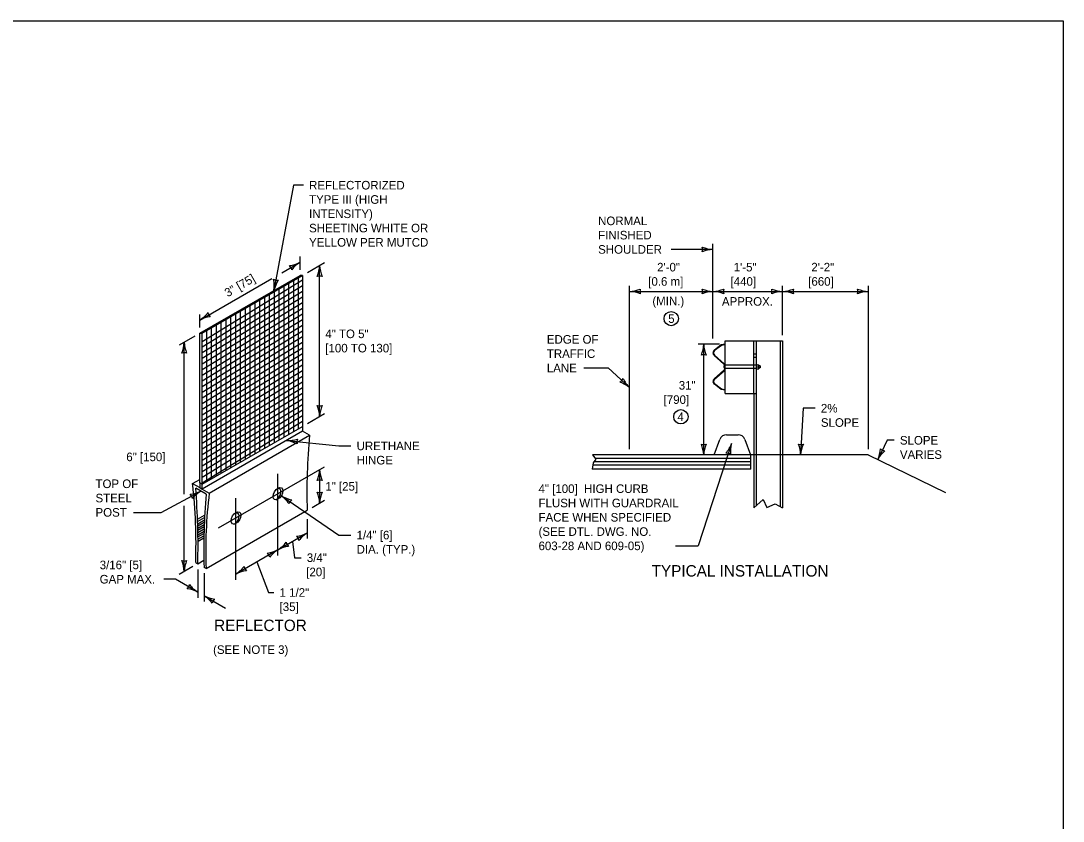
# Model space of a CAD drawing. Extents: x 49991.4 to 50021, y 49987.6 to 50011.4.
# Drawn here: x 50009.46 to 50016.75, y 49993.4 to 49999 of the extents above; entities that cross this region are included whole.
import ezdxf

# ---------------------------------------------------------------- set-up
doc = ezdxf.new("R2010")
doc.units = 0
for name, color, linetype in [('Level 1', 7, 'Continuous'), ('Level 2', 7, 'Continuous'), ('Level 3', 7, 'Continuous'), ('Level 4', 7, 'Continuous'), ('Level 5', 7, 'Continuous')]:
    doc.layers.add(name, color=color, linetype=linetype)

msp = doc.modelspace()

# ---------------------------------------------------------------- linework, layer by layer
at = {"layer": 'Level 1'}
for p, q in [((50010.7126, 49996.8127), (50011.4141, 49997.2177)), ((50010.7295, 49996.8127), (50011.4309, 49997.2177)), ((50011.4037, 49996.1458), (50011.4037, 49997.202)), ((50011.4309, 49997.2177), (50011.4141, 49997.2177)), ((50011.4309, 49997.2177), (50011.4309, 49996.1615)), ((50010.7295, 49996.7565), (50011.4309, 49997.1868)), ((50010.7295, 49996.7169), (50011.4309, 49997.1472)), ((50011.2687, 49996.0679), (50011.2687, 49997.124)), ((50011.3025, 49996.0874), (50011.3025, 49997.1435)), ((50011.3362, 49996.1069), (50011.3362, 49997.163)), ((50011.37, 49996.1263), (50011.37, 49997.1825)), ((50010.7295, 49996.6773), (50011.4309, 49997.1076)), ((50010.7295, 49996.6378), (50011.4309, 49997.068)), ((50011.1675, 49996.0094), (50011.1675, 49997.0656)), ((50011.2012, 49996.0289), (50011.2012, 49997.085)), ((50011.235, 49996.0484), (50011.235, 49997.1045)), ((50010.7295, 49996.5982), (50011.4309, 49997.0284)), ((50010.7295, 49996.5586), (50011.4309, 49996.9888)), ((50011.0325, 49995.9315), (50011.0325, 49996.9876)), ((50011.0662, 49995.951), (50011.0662, 49997.0071)), ((50011.1, 49995.9705), (50011.1, 49997.0266)), ((50011.1337, 49995.9899), (50011.1337, 49997.0461)), ((50010.7295, 49996.519), (50011.4309, 49996.9492)), ((50010.7295, 49996.4794), (50011.4309, 49996.9096)), ((50010.8975, 49995.8535), (50010.8975, 49996.9097)), ((50010.9312, 49995.873), (50010.9312, 49996.9292)), ((50010.965, 49995.8925), (50010.965, 49996.9486)), ((50010.9987, 49995.912), (50010.9987, 49996.9681)), ((50010.7295, 49996.4398), (50011.4309, 49996.87)), ((50010.7295, 49996.4002), (50011.4309, 49996.8304)), ((50010.7625, 49995.7756), (50010.7625, 49996.8317)), ((50010.7962, 49995.7951), (50010.7962, 49996.8512)), ((50010.83, 49995.8146), (50010.83, 49996.8707)), ((50010.8637, 49995.8341), (50010.8637, 49996.8902)), ((50010.7126, 49995.7663), (50010.7126, 49996.8127)), ((50010.7126, 49996.8127), (50010.7295, 49996.8127)), ((50010.7295, 49995.7565), (50010.7295, 49996.8127)), ((50010.7295, 49996.3606), (50011.4309, 49996.7909)), ((50014.3868, 49996.7592), (50014.7881, 49996.7592)), ((50014.3868, 49996.392), (50014.3868, 49996.7592)), ((50014.6028, 49996.7592), (50014.6028, 49995.9612)), ((50014.7722, 49996.7592), (50014.7722, 49995.9612)), ((50014.7881, 49996.7592), (50014.7881, 49995.9612)), ((50010.7295, 49996.321), (50011.4309, 49996.7513)), ((50010.7295, 49996.2814), (50011.4309, 49996.7117)), ((50014.3595, 49996.7313), (50014.3116, 49996.6954)), ((50014.3608, 49996.7284), (50014.3134, 49996.6929)), ((50014.3868, 49996.7362), (50014.3595, 49996.7313)), ((50014.3868, 49996.7329), (50014.3608, 49996.7284)), ((50010.7295, 49996.2418), (50011.4309, 49996.6721)), ((50010.7295, 49996.2022), (50011.4309, 49996.6325)), ((50014.3102, 49996.657), (50014.3785, 49996.5975)), ((50014.3122, 49996.6594), (50014.3806, 49996.5998)), ((50010.7295, 49996.1626), (50011.4309, 49996.5929)), ((50010.7295, 49996.1231), (50011.4309, 49996.5533)), ((50014.3102, 49996.4944), (50014.3783, 49996.5538)), ((50014.3122, 49996.4921), (50014.3817, 49996.5526)), ((50014.3853, 49996.578), (50014.3775, 49996.578)), ((50014.6028, 49996.5943), (50014.6044, 49996.5943)), ((50014.6028, 49996.5614), (50014.6044, 49996.5614)), ((50014.6044, 49996.5943), (50014.6044, 49996.5778)), ((50014.6044, 49996.5912), (50014.6217, 49996.5912)), ((50014.6044, 49996.578), (50014.6217, 49996.578)), ((50014.6044, 49996.5778), (50014.6044, 49996.5614)), ((50014.6044, 49996.5648), (50014.6217, 49996.5648)), ((50014.6217, 49996.578), (50014.6217, 49996.5912)), ((50014.6321, 49996.5858), (50014.6217, 49996.5858)), ((50014.6217, 49996.578), (50014.6217, 49996.5648)), ((50014.6321, 49996.5702), (50014.6217, 49996.5702)), ((50014.6321, 49996.5858), (50014.6321, 49996.5702)), ((50010.7295, 49996.0835), (50011.4309, 49996.5137)), ((50010.7295, 49996.0439), (50011.4309, 49996.4741)), ((50010.7295, 49996.0043), (50011.4309, 49996.4345)), ((50010.7295, 49995.9647), (50011.4309, 49996.3949)), ((50014.3595, 49996.4197), (50014.3116, 49996.456)), ((50014.3608, 49996.4227), (50014.3134, 49996.4586)), ((50014.3868, 49996.4149), (50014.3595, 49996.4197)), ((50014.3868, 49996.4182), (50014.3608, 49996.4227)), ((50010.7295, 49995.9251), (50011.4309, 49996.3553)), ((50014.3868, 49996.392), (50014.6028, 49996.392)), ((50014.5869, 49996.392), (50014.5869, 49995.9612)), ((50010.7295, 49995.8855), (50011.4309, 49996.3157)), ((50010.7295, 49995.8459), (50011.4309, 49996.2761)), ((50010.7295, 49995.8063), (50011.4309, 49996.2366)), ((50010.7295, 49995.7667), (50011.4309, 49996.197)), ((50010.7295, 49995.7565), (50011.4309, 49996.1615)), ((50011.4309, 49996.1278), (50010.7295, 49995.7228)), ((50011.4309, 49996.1615), (50011.4309, 49996.1278)), ((50011.4309, 49996.1574), (50011.4309, 49996.1574)), ((50011.4811, 49996.099), (50011.4309, 49996.1278)), ((50014.3972, 49996.1033), (50014.4772, 49996.1033)), ((50010.7796, 49995.694), (50011.4811, 49996.099)), ((50014.3105, 49995.9612), (50014.3502, 49996.0704)), ((50014.5242, 49996.0704), (50014.5639, 49995.9612)), ((50013.4596, 49995.9612), (50013.4826, 49995.9309)), ((50015.3875, 49995.9612), (50013.4596, 49995.9612)), ((50014.5664, 49995.8613), (50014.5664, 49995.9612)), ((50015.3875, 49995.9612), (50015.9268, 49995.6982)), ((50013.4634, 49995.9064), (50013.456, 49995.8613)), ((50014.5664, 49995.8892), (50013.4606, 49995.8892)), ((50013.4826, 49995.9309), (50013.4634, 49995.9064)), ((50014.5664, 49995.9132), (50013.4687, 49995.9132)), ((50014.5664, 49995.9372), (50013.4778, 49995.9372)), ((50014.5664, 49995.8613), (50013.456, 49995.8613)), ((50010.6627, 49995.7615), (50010.7126, 49995.7903)), ((50010.6627, 49995.7615), (50010.7126, 49995.7327)), ((50010.7295, 49995.7565), (50010.7126, 49995.7663)), ((50010.7126, 49995.7663), (50010.7126, 49995.7327)), ((50010.7295, 49995.7228), (50010.7295, 49995.7565)), ((50010.7295, 49995.7228), (50010.7295, 49995.7565)), ((50010.7577, 49995.6871), (50010.6846, 49995.7293)), ((50010.7126, 49995.7327), (50010.7295, 49995.7228)), ((50010.7295, 49995.7228), (50010.7796, 49995.694)), ((50010.6976, 49995.5112), (50010.7474, 49995.54)), ((50010.6982, 49995.4959), (50010.7466, 49995.5239)), ((50010.7577, 49995.1666), (50011.4642, 49995.5745)), ((50010.6986, 49995.4806), (50010.7458, 49995.5079)), ((50010.6991, 49995.4653), (50010.7451, 49995.4919)), ((50010.6995, 49995.45), (50010.7444, 49995.4759)), ((50010.6999, 49995.4346), (50010.7439, 49995.46)), ((50010.7002, 49995.4192), (50010.7433, 49995.4441)), ((50010.7004, 49995.4037), (50010.7429, 49995.4282)), ((50010.7006, 49995.3883), (50010.7425, 49995.4124)), ((50010.7008, 49995.3728), (50010.7421, 49995.3966)), ((50010.7009, 49995.3572), (50010.7418, 49995.3808)), ((50010.6846, 49995.2088), (50010.6992, 49995.2004)), ((50010.6992, 49995.2004), (50010.7419, 49995.225)), ((50010.7577, 49995.1666), (50010.7431, 49995.1751))]:
    msp.add_line(p, q, dxfattribs=at)
msp.add_lwpolyline([(49999.3835, 49998.9992), (50016.7501, 49998.9992), (50016.7501, 49987.7988), (49999.3835, 49987.7988)], close=True, dxfattribs=at)
for centre, radius, start, end in [((50014.3264, 49996.6757), 0.0247, 126.89692, 228.93931), ((50014.3264, 49996.6757), 0.0216, 126.89692, 228.93931), ((50014.3624, 49996.5725), 0.0246, 310.4718, 353.52997), ((50014.3624, 49996.5789), 0.0246, 6.47003, 48.93931), ((50014.3624, 49996.5789), 0.0277, 28.21928, 48.93931), ((50014.3624, 49996.5725), 0.0277, 314.1015, 331.78072), ((50014.615, 49996.5846), 0.00673, 282.91982, 80.80521), ((50014.615, 49996.5715), 0.00673, 279.19479, 77.08018), ((50014.3264, 49996.4758), 0.0247, 131.06069, 233.10308), ((50014.3264, 49996.4758), 0.0216, 131.06069, 233.10308), ((50014.3972, 49996.0533), 0.05, 90, 159.99404), ((50014.4772, 49996.0533), 0.05, 20.00596, 90), ((50015.6681, 49995.7018), 4.2058, 174.58065, 181.73332), ((50006.9878, 49995.3389), 3.6991, 357.984, 6.55893), ((50005.8293, 49995.3305), 4.8717, 358.46937, 4.69582), ((50015.1622, 49995.3052), 4.4211, 175.04388, 181.68667), ((50013.9812, 49995.2968), 3.2261, 172.92757, 182.31169)]:
    msp.add_arc(centre, radius, start, end, dxfattribs=at)
for centre, major_axis, ratio, start_param, end_param in [((50014.3853, 49996.5779), (0, 0.0118), 0.663267, 0.091019, 3.253139), ((50011.2492, 49995.6861), (0.0228, 0.0395), 0.57735, 3.80014, 6.895622), ((50010.9582, 49995.5157), (0.0214, 0.0371), 0.57735, 3.593264, 7.511454)]:
    msp.add_ellipse(centre, major_axis=major_axis, ratio=ratio, start_param=start_param, end_param=end_param, dxfattribs=at)
for centre, major_axis in [((50011.2598, 49995.6904), (0.0239, 0.0413)), ((50010.9659, 49995.5207), (0.024, 0.0415))]:
    msp.add_ellipse(centre, major_axis=major_axis, ratio=0.57735, dxfattribs=at)
at = {"layer": 'Level 2'}
for centre in [(50014.0096, 49996.9157), (50014.0771, 49996.2287)]:
    msp.add_circle(centre, 0.05, dxfattribs=at)
at = {"layer": 'Level 3'}
for p, q in [((50011.3691, 49997.8491), (50011.2321, 49997.1126)), ((50011.4376, 49997.8491), (50011.3691, 49997.8491)), ((50014.3016, 49996.7762), (50014.3016, 49997.4396)), ((50011.4141, 49997.2577), (50011.4141, 49997.35)), ((50014.3016, 49997.3996), (50014.009, 49997.3996)), ((50011.286, 49997.2361), (50011.4141, 49997.31)), ((50011.4656, 49997.2377), (50011.5859, 49997.3071)), ((50011.5512, 49996.231), (50011.5512, 49997.2871)), ((50010.7126, 49996.905), (50011.2167, 49997.1961)), ((50013.7176, 49996.0012), (50013.7176, 49997.1457)), ((50014.7881, 49996.7992), (50014.7881, 49997.1457)), ((50015.3875, 49997.1457), (50015.3875, 49996.0012)), ((50013.7176, 49997.1057), (50014.3016, 49997.1057)), ((50014.3016, 49997.1057), (50014.7881, 49997.1057)), ((50014.7881, 49997.1057), (50015.3875, 49997.1057)), ((50010.7126, 49996.8527), (50010.7126, 49996.945)), ((50010.6779, 49996.7927), (50010.57, 49996.7303)), ((50010.6046, 49995.686), (50010.6046, 49996.7503)), ((50014.3468, 49996.7362), (50014.197, 49996.7362)), ((50014.237, 49995.9612), (50014.237, 49996.7362)), ((50013.398, 49996.5702), (50013.5682, 49996.5702)), ((50013.5682, 49996.5702), (50013.7176, 49996.4324)), ((50011.4656, 49996.1815), (50011.5859, 49996.251)), ((50014.9315, 49996.2884), (50014.9132, 49995.9612)), ((50015.0162, 49996.2884), (50014.9315, 49996.2884)), ((50011.3196, 49996.0635), (50011.6852, 49996.0251)), ((50014.4314, 49996.0416), (50014.1989, 49995.3254)), ((50015.5186, 49996.0642), (50015.4549, 49995.9284)), ((50015.5686, 49996.0642), (50015.5186, 49996.0642)), ((50011.6852, 49996.0251), (50011.7698, 49996.0251)), ((50011.5512, 49995.8586), (50011.5512, 49995.6248)), ((50010.4432, 49995.5598), (50010.7211, 49995.7082)), ((50011.2837, 49995.6766), (50011.6852, 49995.4009)), ((50010.6046, 49995.1458), (50010.6046, 49995.606)), ((50011.4988, 49995.5945), (50011.5859, 49995.6448)), ((50010.2504, 49995.5598), (50010.4432, 49995.5598)), ((50011.4642, 49995.5126), (50011.4642, 49995.3759)), ((50011.2598, 49995.2979), (50011.4642, 49995.4159)), ((50011.6852, 49995.4009), (50011.7699, 49995.4009)), ((50011.362, 49995.3569), (50011.3759, 49995.2428)), ((50014.0407, 49995.3254), (50014.1989, 49995.3254)), ((50011.2598, 49995.2979), (50010.9659, 49995.1282)), ((50011.3759, 49995.2428), (50011.4218, 49995.2428)), ((50010.6646, 49995.1804), (50010.57, 49995.1258)), ((50010.6992, 49995.1604), (50010.6992, 49994.9618)), ((50010.543, 49995.092), (50010.4608, 49995.092)), ((50010.6992, 49995.0018), (50010.543, 49995.092)), ((50010.7431, 49995.1351), (50010.7431, 49994.9365)), ((50010.7431, 49994.9765), (50010.8932, 49994.8898))]:
    msp.add_line(p, q, dxfattribs=at)
msp.add_lwpolyline([(50011.1128, 49995.2131), (50011.1933, 49994.9992), (50011.2312, 49994.9992)], dxfattribs=at)
for centre, radius, start, end in [((50014.1734, 49997.3996), 0.0548, 342.13882, 17.86118), ((50014.3131, 49997.6323), 0.233, 247.92284, 267.17269), ((50014.3108, 49997.1775), 0.2223, 92.36048, 112.54399), ((50011.3109, 49997.507), 0.2223, 277.45601, 297.63952), ((50011.303, 49997.2459), 0.0548, 12.13882, 47.86118), ((50011.5404, 49997.1143), 0.233, 122.82731, 142.07716), ((50011.3291, 49997.2963), 0.2223, 337.45601, 357.63952), ((50011.7839, 49997.2986), 0.233, 182.82731, 202.07716), ((50011.5512, 49997.1589), 0.0548, 72.13882, 107.86118), ((50011.2556, 49997.2387), 0.0548, 241.60423, 277.32659), ((50011.0012, 49997.1439), 0.233, 352.29272, 11.54257), ((50011.4488, 49997.063), 0.2223, 146.92142, 167.10493), ((50013.7061, 49997.3384), 0.233, 272.82731, 292.07716), ((50013.8458, 49997.1057), 0.0548, 162.13882, 197.86118), ((50014.3108, 49997.3279), 0.2223, 247.45601, 267.63952), ((50014.1734, 49997.1057), 0.0548, 342.13882, 17.86118), ((50014.2901, 49997.3384), 0.233, 272.82731, 292.07716), ((50014.4298, 49997.1057), 0.0548, 162.13882, 197.86118), ((50014.7973, 49997.3279), 0.2223, 247.45601, 267.63952), ((50014.6599, 49997.1057), 0.0548, 342.13882, 17.86118), ((50014.7766, 49997.3384), 0.233, 272.82731, 292.07716), ((50014.9163, 49997.1057), 0.0548, 162.13882, 197.86118), ((50015.3967, 49997.3279), 0.2223, 247.45601, 267.63952), ((50015.2593, 49997.1057), 0.0548, 342.13882, 17.86118), ((50013.7085, 49996.8836), 0.2223, 67.45601, 87.63952), ((50014.3131, 49996.873), 0.233, 92.82731, 112.07716), ((50014.2925, 49996.8836), 0.2223, 67.45601, 87.63952), ((50014.7996, 49996.873), 0.233, 92.82731, 112.07716), ((50014.779, 49996.8836), 0.2223, 67.45601, 87.63952), ((50015.399, 49996.873), 0.233, 92.82731, 112.07716), ((50010.5863, 49997.1008), 0.233, 302.82731, 322.07716), ((50010.8157, 49996.7081), 0.2223, 97.45601, 117.63952), ((50010.8236, 49996.9692), 0.0548, 192.13882, 227.86118), ((50010.3825, 49996.7595), 0.2223, 337.45601, 357.63952), ((50010.8373, 49996.7618), 0.233, 182.82731, 202.07716), ((50014.0149, 49996.7454), 0.2223, 337.45601, 357.63952), ((50014.4697, 49996.7477), 0.233, 182.82731, 202.07716), ((50010.6046, 49996.6221), 0.0548, 72.13882, 107.86118), ((50014.237, 49996.608), 0.0548, 72.13882, 107.86118), ((50013.6234, 49996.5194), 0.0548, 299.45174, 335.1741), ((50013.5683, 49996.2536), 0.233, 50.14023, 69.39008), ((50013.8749, 49996.5895), 0.2223, 204.76893, 224.95244), ((50011.5512, 49996.3592), 0.0548, 252.13882, 287.86118), ((50011.3185, 49996.2195), 0.233, 2.82731, 22.07716), ((50011.7734, 49996.2218), 0.2223, 157.45601, 177.63952), ((50011.3324, 49996.2961), 0.233, 266.83568, 286.08553), ((50011.2873, 49995.8435), 0.2223, 61.46438, 81.64789), ((50011.4471, 49996.0501), 0.0548, 156.14719, 191.86955), ((50014.237, 49996.0894), 0.0548, 252.13882, 287.86118), ((50014.0043, 49995.9497), 0.233, 2.82731, 22.07716), ((50014.4591, 49995.9521), 0.2223, 157.45601, 177.63952), ((50014.223, 49996.1189), 0.2223, 319.46868, 339.65219), ((50014.6563, 49995.9807), 0.233, 164.83998, 184.08983), ((50014.9202, 49996.0892), 0.0548, 248.99463, 284.71699), ((50014.6802, 49995.9625), 0.233, 359.68312, 18.93297), ((50015.1344, 49995.9399), 0.2223, 154.31182, 174.49533), ((50014.3918, 49995.9197), 0.0548, 54.15149, 89.87385), ((50015.2393, 49996.0168), 0.233, 337.68312, 356.93297), ((50015.6521, 49995.8257), 0.2223, 132.31182, 152.49532), ((50015.5094, 49996.0444), 0.0548, 226.99462, 262.71699), ((50011.3291, 49995.8678), 0.2223, 337.45601, 357.63952), ((50011.7839, 49995.8701), 0.233, 182.82731, 202.07716), ((50011.5512, 49995.7304), 0.0548, 72.13882, 107.86118), ((50010.6246, 49995.9085), 0.2223, 275.56316, 295.74667), ((50010.6081, 49995.6478), 0.0548, 10.24597, 45.96833), ((50010.8409, 49995.5084), 0.233, 120.93446, 140.18431), ((50011.1504, 49995.4986), 0.2223, 32.97928, 53.16279), ((50011.4059, 49995.8749), 0.233, 238.35058, 257.60043), ((50011.5512, 49995.753), 0.0548, 252.13882, 287.86118), ((50011.3185, 49995.6133), 0.233, 2.82731, 22.07716), ((50011.7734, 49995.6156), 0.2223, 157.45601, 177.63952), ((50011.3894, 49995.604), 0.0548, 127.66209, 163.38445), ((50011.3611, 49995.6129), 0.2223, 277.45601, 297.63952), ((50011.3532, 49995.3518), 0.0548, 12.13882, 47.86118), ((50011.5905, 49995.2202), 0.233, 122.82731, 142.07716), ((50011.1335, 49995.4937), 0.233, 302.82731, 322.07716), ((50011.3629, 49995.101), 0.2223, 97.45601, 117.63952), ((50011.3708, 49995.362), 0.0548, 192.13882, 227.86118), ((50011.1567, 49995.4949), 0.2223, 277.45601, 297.63952), ((50011.1488, 49995.2338), 0.0548, 12.13882, 47.86118), ((50011.3861, 49995.1021), 0.233, 122.82731, 142.07716), ((50010.6046, 49995.274), 0.0548, 252.13882, 287.86118), ((50010.3719, 49995.1343), 0.233, 2.82731, 22.07716), ((50010.8267, 49995.1366), 0.2223, 157.45601, 177.63952), ((50010.8395, 49995.324), 0.233, 302.82731, 322.07716), ((50011.0769, 49995.1923), 0.0548, 192.13882, 227.86118), ((50011.069, 49994.9313), 0.2223, 97.45601, 117.63952), ((50010.5882, 49995.0659), 0.0548, 312.13882, 347.86118), ((50010.5928, 49994.7945), 0.233, 62.82731, 82.07716), ((50010.8182, 49995.1896), 0.2223, 217.45601, 237.63952), ((50010.6241, 49994.7887), 0.2223, 37.45601, 57.63952), ((50010.8495, 49995.1838), 0.233, 242.82731, 262.07716), ((50010.8541, 49994.9124), 0.0548, 132.13882, 167.86118)]:
    msp.add_arc(centre, radius, start, end, dxfattribs=at)
at = {"layer": 'Level 4'}
for p, q in [((50014.5869, 49996.392), (50014.5869, 49996.7592)), ((50014.6028, 49996.6679), (50014.5869, 49996.6679)), ((50014.6028, 49996.6435), (50014.5869, 49996.6435)), ((50014.6028, 49996.5902), (50014.388, 49996.5902)), ((50014.6028, 49996.5657), (50014.388, 49996.5657)), ((50014.5869, 49995.9612), (50014.5869, 49995.5904)), ((50014.6028, 49995.9612), (50014.6028, 49995.6048)), ((50014.7722, 49995.9612), (50014.7722, 49995.6)), ((50014.7881, 49995.9612), (50014.7881, 49995.5915)), ((50014.5869, 49995.5904), (50014.653, 49995.6503)), ((50014.653, 49995.6503), (50014.6774, 49995.5944)), ((50014.6774, 49995.5944), (50014.7369, 49995.6189)), ((50014.7369, 49995.6189), (50014.7881, 49995.5915))]:
    msp.add_line(p, q, dxfattribs=at)
at = {"layer": 'Level 5'}
for p, q in [((50010.8453, 49995.4511), (50011.5859, 49995.8786)), ((50011.2598, 49995.2579), (50011.2598, 49995.8293)), ((50010.9659, 49995.0882), (50010.9659, 49995.6598))]:
    msp.add_line(p, q, dxfattribs=at)

# ---------------------------------------------------------------- texts
at = {"layer": 'Level 2'}
for s, height, p in [('REFLECTORIZED', 0.06, (50011.4776, 49997.8191)), ('TYPE III (HIGH', 0.06, (50011.4776, 49997.7191)), ('INTENSITY)', 0.06, (50011.4776, 49997.6191)), ('SHEETING WHITE OR', 0.06, (50011.4776, 49997.5191)), ('NORMAL', 0.06, (50013.4987, 49997.5696)), ('FINISHED', 0.06, (50013.4987, 49997.4696)), ('YELLOW PER MUTCD', 0.06, (50011.4776, 49997.4191)), ('SHOULDER', 0.06, (50013.4987, 49997.3696)), ('2\'-0"', 0.06, (50013.9111, 49997.2457)), ('1\'-5"', 0.06, (50014.4464, 49997.2457)), ('2\'-2"', 0.06, (50014.9893, 49997.2457)), ('[0.6 m]', 0.06, (50013.8489, 49997.1457)), ('[440]', 0.06, (50014.4246, 49997.1457)), ('[660]', 0.06, (50014.9676, 49997.1457)), ('(MIN.)', 0.06, (50013.8779, 49997.0092)), ('APPROX.', 0.06, (50014.3642, 49997.0057)), ('5', 0.06, (50013.9886, 49996.8854)), ('4" TO 5"', 0.06, (50011.5912, 49996.779)), ('EDGE OF', 0.06, (50013.14, 49996.7402)), ('[100 TO 130]', 0.06, (50011.5912, 49996.679)), ('TRAFFIC', 0.06, (50013.14, 49996.6402)), ('LANE', 0.06, (50013.14, 49996.5402)), ('31"', 0.06, (50014.0624, 49996.4187)), ('[790]', 0.06, (50013.9566, 49996.3187)), ('2% ', 0.06, (50015.0562, 49996.2584)), ('4', 0.06, (50014.0532, 49996.1987)), ('SLOPE', 0.06, (50015.0562, 49996.1584)), ('URETHANE', 0.06, (50011.8098, 49995.9951)), ('SLOPE', 0.06, (50015.6086, 49996.0342)), ('6" [150]', 0.06, (50010.1996, 49995.918)), ('HINGE', 0.06, (50011.8098, 49995.8951)), ('VARIES', 0.06, (50015.6086, 49995.9342)), ('TOP OF', 0.06, (50009.9843, 49995.7298)), ('1" [25]', 0.06, (50011.5912, 49995.7117)), ('4" [100]  HIGH CURB ', 0.06, (50013.082, 49995.6954)), ('STEEL', 0.06, (50009.9843, 49995.6298)), ('POST', 0.06, (50009.9843, 49995.5298)), ('FLUSH WITH GUARDRAIL ', 0.06, (50013.082, 49995.5954)), ('FACE WHEN SPECIFIED', 0.06, (50013.082, 49995.4954)), ('(SEE DTL. DWG. NO.', 0.06, (50013.082, 49995.3954)), ('1/4" [6]', 0.06, (50011.8098, 49995.3709)), ('DIA. (TYP.)', 0.06, (50011.8098, 49995.2709)), ('603-28 AND 609-05)', 0.06, (50013.082, 49995.2954)), ('3/16" [5]', 0.06, (50010.0135, 49995.162)), ('TYPICAL INSTALLATION', 0.08, (50013.8725, 49995.1105)), ('GAP MAX.', 0.06, (50010.0135, 49995.062)), ('REFLECTOR', 0.08, (50010.8136, 49994.7292)), ('(SEE NOTE 3)', 0.06, (50010.8063, 49994.5692))]:
    msp.add_text(s, height=height, dxfattribs=at).set_placement(p)
for s, rotation, p in [('3" [75]', 30, (50010.9084, 49997.0643)), ('3/4"', 360, (50011.4618, 49995.2128)), ('[20]', 360, (50011.4576, 49995.1128)), ('1 1/2"', 0, (50011.2712, 49994.9692)), ('[35]', 0, (50011.2712, 49994.8692))]:
    msp.add_text(s, height=0.06, rotation=rotation, dxfattribs=at).set_placement(p)

doc.saveas('drawing.dxf')
